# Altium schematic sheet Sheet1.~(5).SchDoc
size A; SheetNumber: 1; SheetTotal: 1
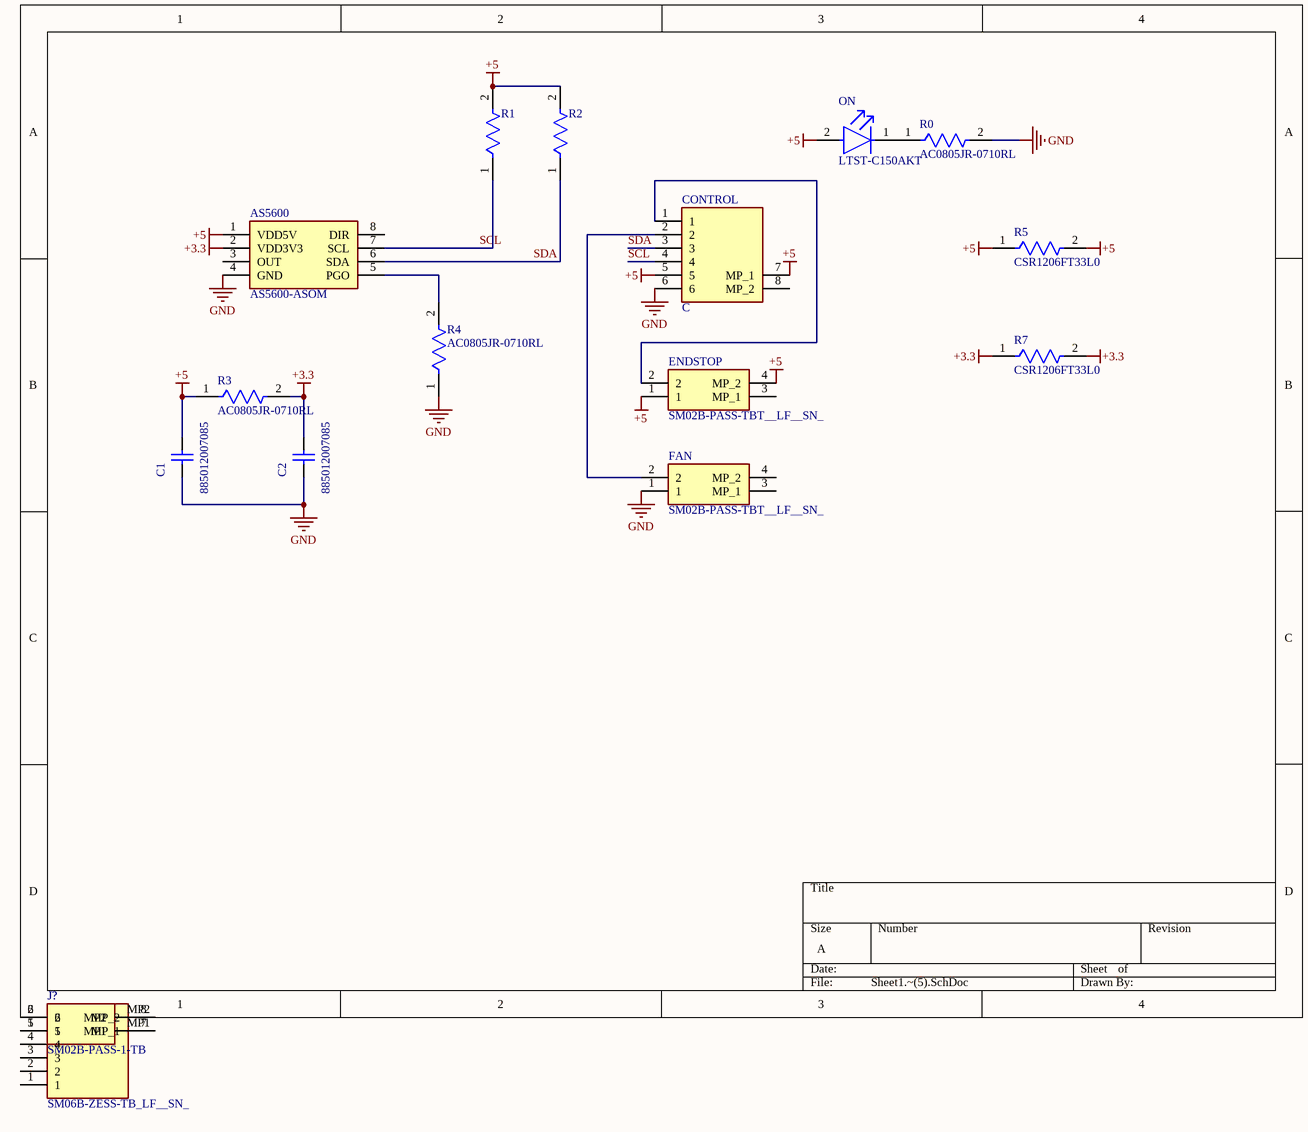
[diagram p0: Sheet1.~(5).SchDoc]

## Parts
(Parts that share a designator on the sheet are numbered #1, #2 ... from top to bottom, then left to right.)
AS5600  AS5600-ASOM  [SOIC127P600X175-8N]
C1  885012007085  [WCAP-CSGP_0805_L2W1.25H0.6_Reflow]
C2  885012007085  [WCAP-CSGP_0805_L2W1.25H0.6_Reflow]
CONTROL  C  [SM06BZESSTBLFSN]
ENDSTOP  SM02B-PASS-TBT__LF__SN_  [SM02BPASSTBTLFSN]
FAN  SM02B-PASS-TBT__LF__SN_  [SM02BPASSTBTLFSN]
J?#1  SM06B-ZESS-TB_LF__SN_  [SM06BZESSTBLFSN]
J?#2  SM02B-PASS-1-TB  [SM02BPASS1TB]
ON  LTST-C150AKT  [FP-LTST-C150AKT-MFG]
R0  AC0805JR-0710RL  [FP-AC0805-MFG]
R1  AC0805JR-0710RL  [FP-AC0805-MFG]  (value not drawn)
R2  AC0805JR-0710RL  [FP-AC0805-MFG]  (value not drawn)
R3  AC0805JR-0710RL  [FP-AC0805-MFG]
R4  AC0805JR-0710RL  [FP-AC0805-MFG]
R5  CSR1206FT33L0  [FP-CSR1206-MFG]
R7  CSR1206FT33L0  [FP-CSR1206-MFG]

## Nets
+3.3: AS5600.2(VDD3V3) C2.2 R3.2 R7.1 R7.2
+5: AS5600.1(VDD5V) C1.2 CONTROL.5 CONTROL.7(MP_1) ENDSTOP.1 ENDSTOP.4(MP_2) ON.2(A) R1.2 R2.2 R3.1 R5.1 R5.2
GND: AS5600.4(GND) C1.1 C2.1 CONTROL.6 FAN.1 R0.2 R4.1
SCL: AS5600.7(SCL) CONTROL.4 R1.1
SDA: AS5600.6(SDA) CONTROL.3 R2.1
NetAS5600_5: AS5600.5(PGO) R4.2
NetCONTROL_1: CONTROL.1 ENDSTOP.2
NetCONTROL_2: CONTROL.2 FAN.2
NetJ?#1_5: J?#1.5 J?#2.1
NetJ?#1_6: J?#1.6 J?#2.2
NetON_1: ON.1(C) R0.1

Not connected (* = marked no-connect by the designer): AS5600 3(OUT) 8(DIR); CONTROL 8(MP_2); ENDSTOP 3(MP_1); FAN 3(MP_1) 4(MP_2); J?#1 1 2 3 4 7(MP_1) 8(MP_2); J?#2 MP1 MP2

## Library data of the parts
AS5600 = AS5600-ASOM: Integrated Circuit; Manufacturer_Name: ams OSRAM
C1 C2 = CMP-03913-89205616-2: Cap, Mlcc, 330PF, 100V, C0G/NP0, 0805;; Insulation Resistance: 10GΩ
CONTROL J?#1 = SM06B-ZESS-TB_LF__SN_: Connector; Manufacturer_Name: JST (JAPAN SOLDERLESS TERMINALS); Manufacturer_Part_Number: SM06B-ZESS-TB(LF)(SN)
ENDSTOP FAN = SM02B-PASS-TBT__LF__SN_: Connector; Manufacturer_Name: JST (JAPAN SOLDERLESS TERMINALS); Manufacturer_Part_Number: SM02B-PASS-TBT (LF)(SN)
J?#2 = SM02B-PASS-1-TB: Connector; Manufacturer_Name: JST (JAPAN SOLDERLESS TERMINALS)
ON = CMP-22017-000004-1: LED AMBER CLEAR SMD; Manufacturer: Lite-On; Luminous Intensity: 6mcd; Viewing Angle: 130°; Wavelength: 602nm; Reverse Voltage: 5V; Forward Current: 30mA; Led Orientation: Top View; Power Dissipation: 100mW; Description: Amber 602nm LED Indication - Discrete 2.1V 1206 (3216 Metric); Peak Emmision Wavelength: 610nm; Forward Voltage: 2.1V
R0-R4 = CMP-03412-037687-1: RES SMD 10 OHM 5% 1/8W 0805; Manufacturer: Yageo; Automotive Grade: Grade 0; Value: 10Ω; Voltage Rating: 150V; Tolerance: 0.05
R5 R7 = CMP-26527-002831-1: General Purpose Thick Film Chip Resistor, 1206, 33mΩ, 1%, 0.5W; Resistance: 33mR; Temperature Coefficient: 100ppm/°C; Max Power Dissipation: 500mW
